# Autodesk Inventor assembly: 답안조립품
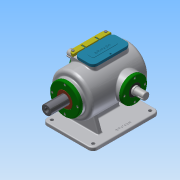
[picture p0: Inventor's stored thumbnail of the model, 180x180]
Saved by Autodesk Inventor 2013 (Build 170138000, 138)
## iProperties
Created: 2018-08
Part Number: 답안조립품
Document SubType Name: Assembly
Designer: user
Mass: 7433.62 g
Surface Area: 4486.61 cm^2
Volume: 2026.97 cm^3
Density: 3.66735 g/cm^3
Author: user
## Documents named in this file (15)
- C:\Users\user\Desktop\380808V1014\380808V1014\공용부품_20180825_1\답안조립품.iam
- C:\Users\user\Desktop\380808V1014\380808V1014\공용부품_20180825_1\본체.ipt
- C:\Users\user\Desktop\380808V1014\380808V1014\공용부품_20180825_1\고정플레이트.ipt
- C:\Users\user\Desktop\380808V1014\380808V1014\공용부품_20180825_1\베어링 6205.ipt
- 베어링 6205.ipt
- C:\Users\user\Desktop\380808V1014\380808V1014\공용부품_20180825_1\볼트 M4x0.7.ipt
- C:\Users\user\Desktop\380808V1014\380808V1014\공용부품_20180825_1\부시.ipt
- C:\Users\user\Desktop\380808V1014\380808V1014\공용부품_20180825_1\상부커버.ipt
- C:\Users\user\Desktop\380808V1014\380808V1014\공용부품_20180825_1\슬라이드 커버.ipt
- C:\Users\user\Desktop\380808V1014\380808V1014\공용부품_20180825_1\슬라이드.ipt
- C:\Users\user\Desktop\380808V1014\380808V1014\공용부품_20180825_1\오일 실 25 38 8.ipt
- C:\Users\user\Desktop\380808V1014\380808V1014\공용부품_20180825_1\육각머리볼트 M4.ipt
- C:\Users\user\Desktop\380808V1014\380808V1014\공용부품_20180825_1\축 커버.ipt
- C:\Users\user\Desktop\380808V1014\380808V1014\공용부품_20180825_1\편심축.ipt
- C:\Users\user\Desktop\380808V1014\380808V1014\공용부품_20180825_1\가변스프링.ipt
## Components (14 placed, 3 different names)
1. 고정플레이트:1 — 플러쉬:44
2. 가변스프링:1
3. M4x0.7:1
4. M4x0.7:4
5. M4x0.7:5
6. M4x0.7:6
7. M4x0.7:2
8. M4x0.7:7
9. M4x0.7:8
10. M4x0.7:9
11. M4x0.7:3
12. M4x0.7:10
13. M4x0.7:11
14. M4x0.7:12
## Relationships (1: Flush 1)
- 플러쉬:44 [Flush]: 고정플레이트:1
